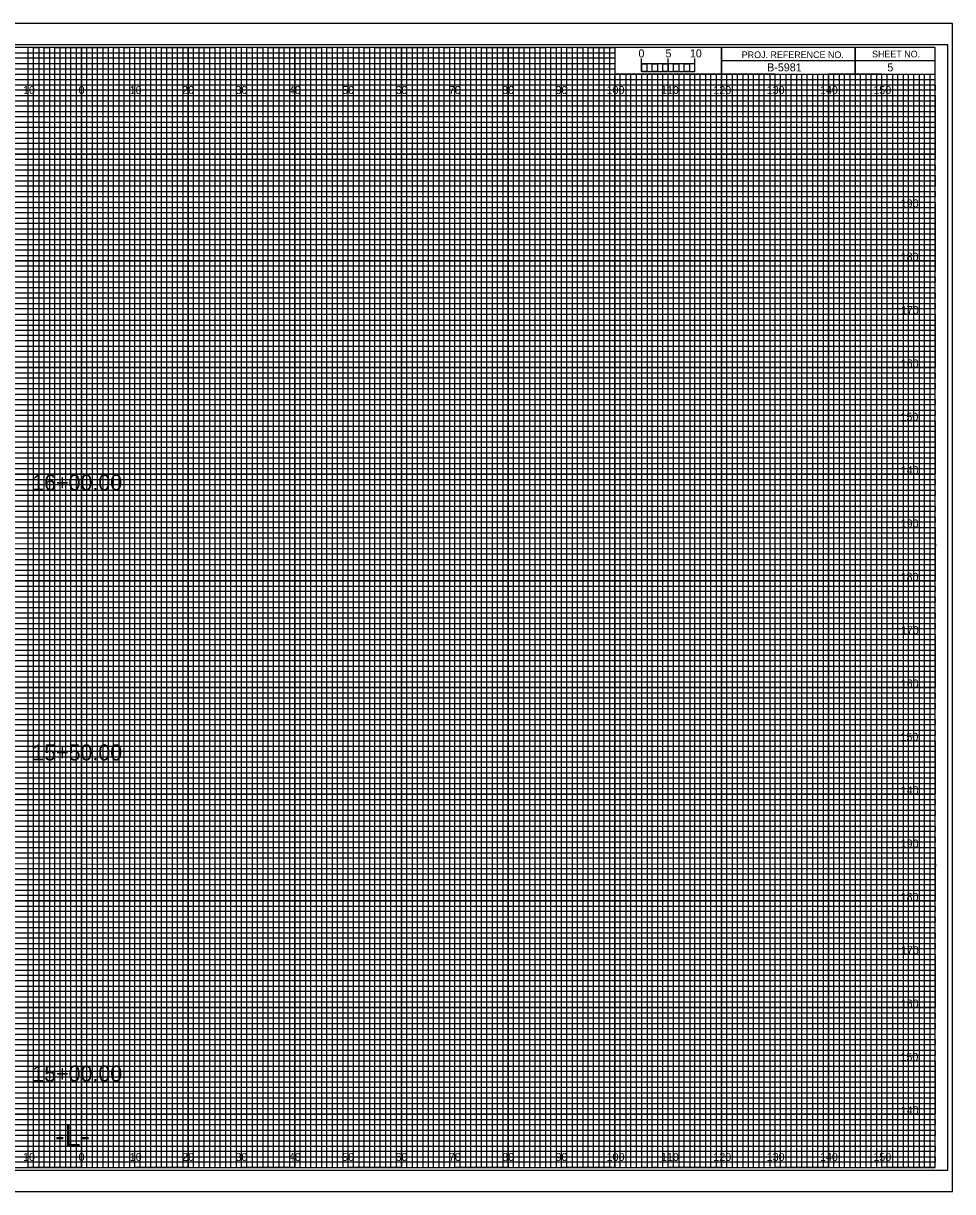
# Model space of a CAD drawing. Extents: x -13 to 323, y -5 to 1754.
# Drawn here: x 149.1 to 323.3, y 215.5 to 434.5 of the extents above; entities that cross this region are included whole.
import ezdxf

# ---------------------------------------------------------------- set-up
doc = ezdxf.new("R2010")
doc.units = 0
for name, color, linetype in [('Exist Cross Section Cell', 7, 'Continuous'), ('Exist XS Center Line Elevation Label', 7, 'Continuous'), ('Exist XS Ground Line', 7, 'Continuous'), ('Prop CMT Concrete Structures', 7, 'Continuous'), ('Prop CMT Guardrail Graphics', 7, 'Continuous'), ('Prop CMT Pvmt Course 1', 7, 'Continuous'), ('Prop CMT Pvmt Course 2', 7, 'Continuous'), ('Prop CMT Pvmt Course 3', 7, 'Continuous'), ('Prop CMT Pvmt Surface', 7, 'Continuous'), ('Prop CMT Shld Paved Course 1', 7, 'Continuous'), ('Prop CMT Shld Paved Course 2', 7, 'Continuous'), ('Prop CMT Shld Paved Course 3', 7, 'Continuous'), ('Prop CMT Subgrade Earthwork', 7, 'Continuous'), ('Prop XS Ditch Standard Text', 7, 'Continuous'), ('Prop XS SE Text', 7, 'Continuous'), ('Prop XS Side Slope Text', 7, 'Continuous'), ('Scratch_Level_0', 7, 'Continuous')]:
    doc.layers.add(name, color=color, linetype=linetype)

msp = doc.modelspace()

# ---------------------------------------------------------------- linework, layer by layer
at = {"layer": 'Exist XS Center Line Elevation Label'}
for points in [[(145, 220), (155, 220), (155, 430), (165, 430), (165, 220), (175, 220), (175, 430), (185, 430), (185, 220), (195, 220), (195, 430), (205, 430), (205, 220), (215, 220), (215, 430), (225, 430), (225, 220), (235, 220), (235, 430), (245, 430), (245, 220), (255, 220), (255, 430), (259.93, 430), (260, 430), (260, 425), (264.99, 425), (264.99, 220), (275, 220), (275, 425), (285, 425), (285, 220), (295, 220), (295, 425), (305, 425), (305, 220), (315, 220), (315, 425)], [(0, 425), (275, 425)], [(0, 405), (320, 405), (320, 415), (0, 415)], [(0, 385), (320, 385), (320, 395), (0, 395)], [(0, 365), (320, 365), (320, 375), (0, 375)], [(0, 345), (320, 345), (320, 355), (0, 355)], [(0, 325), (320, 325), (320, 335), (0, 335)], [(0, 305), (320, 305), (320, 315), (0, 315)], [(0, 285), (320, 285), (320, 295), (0, 295)], [(0, 265), (320, 265), (320, 275), (0, 275)], [(0, 245), (320, 245), (320, 255), (0, 255)], [(0, 225), (320, 225), (320, 235), (0, 235)]]:
    msp.add_lwpolyline(points, dxfattribs=at)
at = {"layer": 'Exist XS Ground Line'}
for p, q in [((150, 430), (140, 430)), ((150, 220), (150, 430)), ((170, 430), (160, 430)), ((160, 430), (160, 220)), ((170, 220), (170, 430)), ((190, 430), (180, 430)), ((180, 430), (180, 220)), ((190, 220), (190, 430)), ((210, 430), (200, 430)), ((200, 430), (200, 220)), ((210, 220), (210, 430)), ((230, 430), (220, 430)), ((220, 430), (220, 220)), ((230, 220), (230, 430)), ((250, 430), (240, 430)), ((240, 430), (240, 220)), ((250, 220), (250, 430)), ((260, 430), (260, 220)), ((270, 220), (270, 425)), ((290, 425), (280, 425)), ((280, 425), (280, 220)), ((290, 220), (290, 425)), ((310, 425), (300, 425)), ((300, 425), (300, 220)), ((310, 220), (310, 425)), ((160, 220), (150, 220)), ((180, 220), (170, 220)), ((200, 220), (190, 220)), ((220, 220), (210, 220)), ((240, 220), (230, 220)), ((260, 220), (250, 220)), ((280, 220), (270, 220)), ((300, 220), (290, 220)), ((320, 220), (310, 220)), ((320, 220), (320, 220))]:
    msp.add_line(p, q, dxfattribs=at)
for points in [[(0, 420), (320, 420), (320, 410), (0, 410)], [(0, 400), (320, 400), (320, 390), (0, 390)], [(0, 380), (320, 380), (320, 370), (0, 370)], [(0, 360), (320, 360), (320, 350), (0, 350)], [(0, 340), (320, 340), (320, 330), (0, 330)], [(0, 320), (320, 320), (320, 310), (0, 310)], [(0, 300), (320, 300), (320, 290), (0, 290)], [(0, 280), (320, 280), (320, 270), (0, 270)], [(0, 260), (320, 260), (320, 250), (0, 250)], [(0, 240), (320, 240), (320, 230), (0, 230)]]:
    msp.add_lwpolyline(points, dxfattribs=at)
at = {"layer": 'Prop CMT Pvmt Course 1'}
for p, q in [((323.3, 434.5), (-13.4, 434.5)), ((-13.4, 215.5), (323.3, 215.5))]:
    msp.add_line(p, q, dxfattribs=at)
at = {"layer": 'Prop CMT Pvmt Course 2'}
msp.add_lwpolyline([(-13.4, 215.5), (323.3, 215.5), (323.3, 434.5), (-13.4, 434.5)], close=True, dxfattribs=at)
at = {"layer": 'Prop CMT Pvmt Course 3'}
msp.add_lwpolyline([(-10.8, 219.5), (322.4, 219.5), (322.4, 430.5), (-10.8, 430.5)], close=True, dxfattribs=at)
at = {"layer": 'Prop CMT Shld Paved Course 1'}
for p, q in [((305, 430), (305, 425)), ((305, 425), (305, 430)), ((280, 427.5), (280, 425)), ((320, 427.49), (280, 427.49)), ((280, 425), (320, 425))]:
    msp.add_line(p, q, dxfattribs=at)
for points in [[(320, 430), (0, 430), (0, 220), (320, 220)], [(280, 430), (260, 430), (260, 425.03), (280, 425.03)], [(320, 430), (280, 430), (280, 425), (320, 425)]]:
    msp.add_lwpolyline(points, close=True, dxfattribs=at)
at = {"layer": 'Prop CMT Shld Paved Course 2'}
for p, q in [((267, 425), (266.01, 425)), ((266.01, 425), (266.01, 220)), ((267, 220), (267, 425)), ((269, 425), (268, 425)), ((268, 425), (268, 220)), ((269, 220), (269, 425)), ((266.01, 220), (265, 220)), ((268, 220), (267, 220))]:
    msp.add_line(p, q, dxfattribs=at)
for points in [[(150, 220), (151, 220), (151, 430), (152, 430), (152, 220)], [(152, 220), (153, 220), (153, 430), (154, 430), (154, 220)], [(155, 220), (156, 220), (156, 430), (157, 430), (157, 220)], [(157, 220), (158, 220), (158, 430), (159, 430), (159, 220)], [(160, 220), (161, 220), (161, 430), (162, 430), (162, 220)], [(162, 220), (163, 220), (163, 430), (164, 430), (164, 220)], [(165, 220), (166, 220), (166, 430), (167, 430), (167, 220)], [(167, 220), (168, 220), (168, 430), (169, 430), (169, 220)], [(170, 220), (171, 220), (171, 430), (172, 430), (172, 220)], [(172, 220), (173, 220), (173, 430), (174, 430), (174, 220)], [(175, 220), (176, 220), (176, 430), (177, 430), (177, 220)], [(177, 220), (178, 220), (178, 430), (179, 430), (179, 220)], [(180, 220), (181, 220), (181, 430), (182, 430), (182, 220)], [(182, 220), (183, 220), (183, 430), (184, 430), (184, 220)], [(185, 220), (186, 220), (186, 430), (187, 430), (187, 220)], [(187, 220), (188, 220), (188, 430), (189, 430), (189, 220)], [(190, 220), (191, 220), (191, 430), (192, 430), (192, 220)], [(192, 220), (193, 220), (193, 430), (194, 430), (194, 220)], [(195, 220), (196, 220), (196, 430), (197, 430), (197, 220)], [(197, 220), (198, 220), (198, 430), (199, 430), (199, 220)], [(200, 220), (201, 220), (201, 430), (202, 430), (202, 220)], [(202, 220), (203, 220), (203, 430), (204, 430), (204, 220)], [(205, 220), (206, 220), (206, 430), (207, 430), (207, 220)], [(207, 220), (208, 220), (208, 430), (209, 430), (209, 220)], [(210, 220), (211, 220), (211, 430), (212, 430), (212, 220)], [(212, 220), (213, 220), (213, 430), (214, 430), (214, 220)], [(215, 220), (216, 220), (216, 430), (217, 430), (217, 220)], [(217, 220), (218, 220), (218, 430), (219, 430), (219, 220)], [(220, 220), (221, 220), (221, 430), (222, 430), (222, 220)], [(222, 220), (223, 220), (223, 430), (224, 430), (224, 220)], [(225, 220), (226, 220), (226, 430), (227, 430), (227, 220)], [(227, 220), (228, 220), (228, 430), (229, 430), (229, 220)], [(230, 220), (231, 220), (231, 430), (232, 430), (232, 220)], [(232, 220), (233, 220), (233, 430), (234, 430), (234, 220)], [(235, 220), (236, 220), (236, 430), (237, 430), (237, 220)], [(237, 220), (238, 220), (238, 430), (239, 430), (239, 220)], [(240, 220), (241, 220), (241, 430), (242, 430), (242, 220)], [(242, 220), (243, 220), (243, 430), (244, 430), (244, 220)], [(245, 220), (246, 220), (246, 430), (247, 430), (247, 220)], [(247, 220), (248, 220), (248, 430), (249, 430), (249, 220)], [(250, 220), (251, 220), (251, 430), (252, 430), (252, 220)], [(252, 220), (253, 220), (253, 430), (254, 430), (254, 220)], [(255, 220), (256, 220), (256, 430), (257, 430), (257, 220)], [(257, 220), (258, 220), (258, 430), (259, 430), (259, 220)], [(260, 220), (261, 220), (261, 425), (262.02, 425), (262.02, 220)], [(262, 220), (263, 220), (263, 425), (263.99, 425), (263.99, 220)], [(270, 220), (270.98, 220), (270.98, 425), (272, 425), (272, 220)], [(272, 220), (273, 220), (273, 425), (274.05, 425), (274.05, 220)], [(275, 220), (276, 220), (276, 425), (277, 425), (277, 220)], [(277, 220), (278, 220), (278, 425), (279, 425), (279, 220)], [(280, 220), (281, 220), (281, 425), (282, 425), (282, 220)], [(282, 220), (283, 220), (283, 425), (284, 425), (284, 220)], [(285, 220), (286, 220), (286, 425), (287, 425), (287, 220)], [(287, 220), (288, 220), (288, 425), (289, 425), (289, 220)], [(290, 220), (291, 220), (291, 425), (292, 425), (292, 220)], [(292, 220), (293, 220), (293, 425), (294, 425), (294, 220)], [(295, 220), (296, 220), (296, 425), (297, 425), (297, 220)], [(297, 220), (298, 220), (298, 425), (299, 425), (299, 220)], [(300, 220), (301, 220), (301, 425), (302, 425), (302, 220)], [(302, 220), (303, 220), (303, 425), (304, 425), (304, 220)], [(305, 220), (306, 220), (306, 425), (307, 425), (307, 220)], [(307, 220), (308, 220), (308, 425), (309, 425), (309, 220)], [(310, 220), (311, 220), (311, 425), (312, 425), (312, 220)], [(312, 220), (313, 220), (313, 425), (314, 425), (314, 220)], [(315, 220), (316, 220), (316, 425), (317, 425), (317, 220)], [(317, 220), (318, 220), (318, 425), (319, 425), (319, 220)]]:
    msp.add_lwpolyline(points, dxfattribs=at)
at = {"layer": 'Prop CMT Shld Paved Course 3'}
for p, q in [((265, 425.49), (265, 427.9)), ((265, 426.9), (265, 427.9)), ((270, 425.49), (270, 427.9)), ((275, 425.49), (275, 427.9)), ((275, 426.9), (275, 427.9))]:
    msp.add_line(p, q, dxfattribs=at)
for points in [[(275, 426.9), (265, 426.9), (265, 425.49), (275, 425.49)], [(265, 426.9), (266, 426.9), (266, 425.49), (265, 425.49)], [(267, 426.9), (268, 426.9), (268, 425.49), (267, 425.49)], [(269, 426.9), (270, 426.9), (270, 425.49), (269, 425.49)], [(271, 426.9), (272, 426.9), (272, 425.49), (271, 425.49)], [(273, 426.9), (274, 426.9), (274, 425.49), (273, 425.49)]]:
    msp.add_lwpolyline(points, close=True, dxfattribs=at)
at = {"layer": 'Prop CMT Subgrade Earthwork'}
for p, q in [((150, 220), (150, 430)), ((160, 220), (160, 430)), ((170, 220), (170, 430)), ((180, 220), (180, 430)), ((190, 220), (190, 430)), ((200, 220), (200, 430)), ((210, 220), (210, 430)), ((220, 220), (220, 430)), ((230, 220), (230, 430)), ((240, 220), (240, 430)), ((250, 220), (250, 430)), ((260, 220), (260, 424.69)), ((270, 220), (270, 424.69)), ((280, 220), (280, 424.69)), ((290, 220), (290, 424.69)), ((300, 220), (300, 424.69)), ((310, 220), (310, 424.69)), ((0, 420), (320, 420)), ((0, 410), (320, 410)), ((0, 400), (320, 400)), ((0, 390), (320, 390)), ((0, 380), (320, 380)), ((0, 370), (320, 370)), ((0, 360), (320, 360)), ((0, 350), (320, 350)), ((0, 340), (320, 340)), ((0, 330), (320, 330)), ((0, 320), (320, 320)), ((0, 310), (320, 310)), ((0, 300), (320, 300)), ((0, 290), (320, 290)), ((0, 280), (320, 280)), ((0, 270), (320, 270)), ((0, 260), (320, 260)), ((0, 250), (320, 250)), ((0, 240), (320, 240)), ((0, 230), (320, 230))]:
    msp.add_line(p, q, dxfattribs=at)
at = {"layer": 'Scratch_Level_0'}
for p, q in [((0, 429), (260, 429)), ((260, 427.98), (0, 427.98)), ((260, 429), (260, 427.98)), ((0, 427), (260, 427)), ((260, 425.89), (0, 425.89)), ((260, 427), (260, 425.89)), ((0, 424), (320, 424))]:
    msp.add_line(p, q, dxfattribs=at)
for points in [[(0, 423), (270, 423), (320, 423), (320, 422), (0, 422)], [(0, 421), (320, 421), (320, 419), (0, 419)], [(0, 418), (320, 418), (320, 417), (0, 416.98)], [(0, 416), (320, 416), (320, 414), (0, 414)], [(0, 413), (320, 413), (320, 412), (0, 412)], [(0, 411), (320, 411), (320, 409), (0, 409)], [(0, 408), (320, 408), (320, 407), (0, 407)], [(0, 406), (320, 406), (320, 404), (0, 404)], [(0, 403), (320, 403), (320, 402), (0, 402)], [(0, 401), (320, 401), (320, 399), (0, 399)], [(0, 398), (320, 398), (320, 397), (0, 397)], [(0, 396), (320, 396), (320, 393.95), (320, 393), (320, 392), (0, 392)], [(0, 394), (320, 394), (320, 393), (0, 393)], [(0, 391), (320, 391), (320, 389), (0, 389.03)], [(0, 389.03), (320, 389), (320, 388), (0, 388)], [(0, 387), (320, 387), (320, 386), (0, 386)], [(0, 384), (320, 384), (320, 383), (0, 383)], [(0, 382), (320, 382), (320, 381), (0, 381)], [(-0.07, 378.89), (320, 378.89), (320, 377.88), (-0.07, 377.88)], [(0, 377), (320, 377), (320, 376), (0, 376)], [(0, 374), (320, 374), (320, 373), (0, 373)], [(0, 372), (320, 372), (320, 371), (0, 371)], [(0, 369), (320, 369), (320, 368), (0, 368)], [(0, 367), (320, 367), (320, 366), (0, 366)], [(0, 364), (320, 364), (320, 363), (0, 363)], [(0, 362), (320, 362), (320, 361), (0, 361)], [(0, 359), (320, 359), (319.99, 357.98), (0, 358)], [(0, 357), (320, 357), (320, 356), (0, 356)], [(0, 354), (320, 354), (320, 353), (0, 353)], [(0, 352), (320, 352), (320, 351), (0, 351)], [(0, 349), (320, 349), (320, 348), (0, 348)], [(0, 347), (320, 347), (320, 346), (0, 346)], [(0, 344), (320, 344), (320, 343), (0, 343)], [(0, 342), (320, 342), (320, 341), (0, 341)], [(0, 339), (320, 339), (320, 338), (0, 338)], [(0, 336.99), (320.07, 336.91), (320, 336), (0, 336)], [(0, 334), (320, 334), (320, 333), (0, 333)], [(0, 332), (320, 332), (320, 331), (0, 331)], [(0, 329), (320, 329), (320, 328), (0, 328)], [(0, 327), (320, 327), (320, 326), (0, 326)], [(0, 324), (320, 324), (320, 323), (0, 323)], [(0, 322), (320, 322), (320, 321), (0, 321)], [(0, 319), (320, 319), (320, 318), (0, 318)], [(0, 317), (320, 317), (320, 316), (0, 316)], [(0, 314), (320, 314), (320, 313), (0, 313)], [(0, 312), (320, 312), (320, 311), (0, 311)], [(0, 309), (320, 309), (320, 308), (0, 308)], [(0, 307), (320, 307), (320, 306), (0, 306)], [(0, 304), (320, 304), (320, 303), (0, 303)], [(0, 302), (320, 302), (320, 301), (0, 301)], [(0, 299), (320, 299), (319.99, 297.98), (0, 298)], [(0, 297), (320, 297), (320, 296), (0, 296)], [(0, 294), (320, 294), (320, 293), (0, 293)], [(0, 292), (320, 292), (320, 291), (0, 291)], [(0, 289), (320, 289), (320, 288), (0, 288)], [(0, 287), (320, 287), (320, 286), (0, 286)], [(0, 284), (320, 284), (320, 283), (0, 283)], [(0, 282), (320, 282), (320, 281), (0, 281)], [(0, 279), (320, 279), (320, 278), (0, 278)], [(0, 276.99), (320.07, 276.91), (320, 276), (0, 276)], [(0, 274), (320, 274), (320, 273), (0, 273)], [(0, 272), (320, 272), (320, 271), (0, 271)], [(0, 269), (320, 269), (320, 268), (0, 268)], [(0, 267), (320, 267), (320, 266), (0, 266)], [(0, 264), (320, 264), (320, 263), (0, 263)], [(0, 262), (320, 262), (320, 261), (0, 261)], [(0, 259), (320, 259), (320, 258), (0, 258)], [(0, 257), (320, 257), (320, 256), (0, 256)], [(0, 254), (320, 254), (320, 253), (0, 253)], [(0, 252), (320, 252), (320, 251), (0, 251)], [(0, 249), (320, 249), (320, 248), (0, 248)], [(0, 247), (320, 247), (320, 246), (0, 246)], [(0, 244), (320, 244), (320, 243), (0, 243)], [(0, 242), (320, 242), (320, 241), (0, 241)], [(0, 239), (320, 239), (320, 238), (0, 238)], [(0, 237), (320, 237), (320, 236), (0, 236)], [(0, 234), (320, 234), (320, 233), (0, 233)], [(0, 232), (320, 232), (320, 231), (0, 231)], [(0, 229), (320, 229), (320, 228), (0, 228)], [(0, 227), (320, 227), (320, 226), (0, 226)], [(0, 224), (320, 224), (320, 223), (0, 223)], [(0, 222), (320, 222), (320, 221), (0, 221)]]:
    msp.add_lwpolyline(points, dxfattribs=at)

# ---------------------------------------------------------------- texts
at = {"layer": 'Exist Cross Section Cell'}
for s, p in [('190', (313.57, 400)), ('180', (313.55, 390)), ('170', (313.61, 380)), ('160', (313.57, 370)), ('150', (313.52, 360)), ('140', (313.57, 350)), ('190', (313.57, 340)), ('180', (313.55, 330)), ('170', (313.61, 320)), ('160', (313.57, 310)), ('150', (313.52, 300)), ('140', (313.57, 290)), ('190', (313.57, 280)), ('180', (313.55, 270)), ('170', (313.61, 260)), ('160', (313.57, 250)), ('150', (313.52, 240)), ('140', (313.57, 230))]:
    msp.add_text(s, height=1.5, dxfattribs=at).set_placement(p)
at = {"layer": 'Prop CMT Concrete Structures'}
msp.add_text('5', height=1.5, dxfattribs=at).set_placement((311.06, 425.5))
at = {"layer": 'Prop CMT Guardrail Graphics'}
for s, p in [('5', (269.47, 428.12)), ('10', (274.04, 428.12))]:
    msp.add_text(s, height=1.5, dxfattribs=at).set_placement(p)
at = {"layer": 'Prop CMT Pvmt Surface'}
for s, p in [('16+00.00', (150.77, 346.94)), ('15+50.00', (150.77, 296.34)), ('15+00.00', (150.77, 236.13))]:
    msp.add_text(s, height=3, dxfattribs=at).set_placement(p)
at = {"layer": 'Prop CMT Shld Paved Course 1'}
for s, p in [('PROJ. REFERENCE NO.', (283.77, 427.99)), ('SHEET NO.', (308.19, 428.12))]:
    msp.add_text(s, height=1.25, dxfattribs=at).set_placement(p)
at = {"layer": 'Prop CMT Shld Paved Course 3'}
msp.add_text('0', height=1.5, dxfattribs=at).set_placement((264.41, 428.12))
at = {"layer": 'Prop XS Ditch Standard Text'}
for s, p in [('10', (149.04, 421.25)), ('0', (159.45, 421.25)), ('0', (159.45, 421.25)), ('10', (169.04, 421.25)), ('20', (178.86, 421.25)), ('30', (188.86, 421.25)), ('40', (198.86, 421.25)), ('50', (208.86, 421.25)), ('60', (218.86, 421.25)), ('70', (228.86, 421.25)), ('80', (238.86, 421.25)), ('90', (248.86, 421.25)), ('100', (258.44, 421.25)), ('110', (268.62, 421.25)), ('120', (278.44, 421.25)), ('130', (288.44, 421.25)), ('140', (298.44, 421.25)), ('150', (308.44, 421.25)), ('10', (149.04, 221.25)), ('0', (159.45, 221.25)), ('0', (159.45, 221.25)), ('10', (169.04, 221.25)), ('20', (178.86, 221.25)), ('30', (188.86, 221.25)), ('40', (198.86, 221.25)), ('50', (208.86, 221.25)), ('60', (218.86, 221.25)), ('70', (228.86, 221.25)), ('80', (238.86, 221.25)), ('90', (248.86, 221.25)), ('100', (258.44, 221.25)), ('110', (268.62, 221.25)), ('120', (278.44, 221.25)), ('130', (288.44, 221.25)), ('140', (298.44, 221.25)), ('150', (308.44, 221.25))]:
    msp.add_text(s, height=1.5, dxfattribs=at).set_placement(p)
at = {"layer": 'Prop XS SE Text'}
msp.add_text('-L-', height=4, dxfattribs=at).set_placement((155.06, 224))
at = {"layer": 'Prop XS Side Slope Text'}
msp.add_text('B-5981', height=1.5, dxfattribs=at).set_placement((288.53, 425.5))

doc.saveas('drawing.dxf')
